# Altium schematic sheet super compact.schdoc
size 292 x 204 mm; Device: A_A4; Symbol: A_A4; Name: A_A4; @Project Name: Roborock fan driver with tacho frequency divider; REV: 1.0; Date: 2024-04-24; Sheet: 1/1; Draw By: David Buezas; Company: Your Company; Convert to PCB: yes; Add into BOM: yes; @Page No: 1; @Page Count: 1; @Schematic Name: Schematic_2; @Board Name: Super compact; @Update Date: 2025-03-17; @Create Time: 09:06:17; @Update Time: 10:07:00; @Page Name: super compact; @Create Date: 2025-03-17
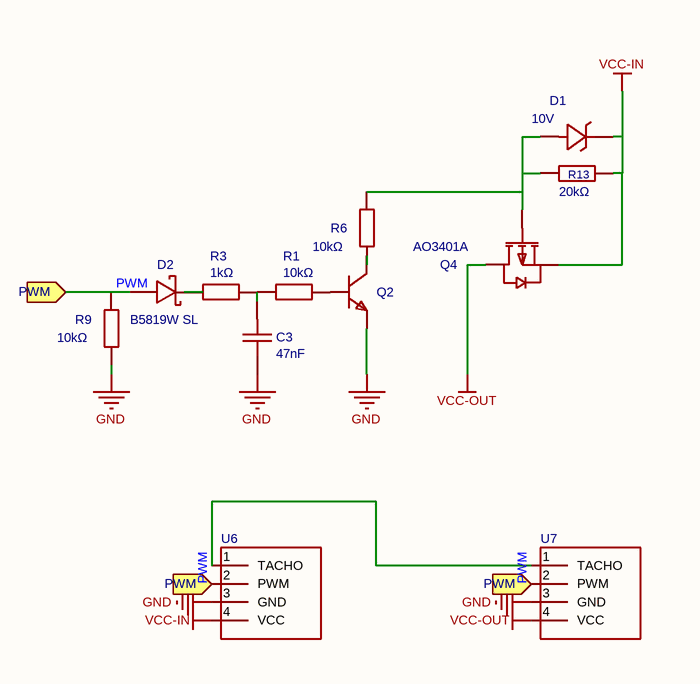
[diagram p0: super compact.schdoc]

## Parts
C3  47nF  [C0603]
D1  Zener Voltage(Nom): 10V  [SOD-123_L2.7-W1.6-LS3.7-RD]  (hidden comment: MMSZ5240B)
D2  B5819W SL  [SOD-123_L2.7-W1.6-LS3.7-RD-1]
Q2  SS8050(RANGE:200-350)  [SOT-23-3_L2.9-W1.3-P1.90-LS2.4-BR]  (value not drawn)
Q4  AO3401A  [SOT-23_L2.9-W1.3-P1.90-LS2.4-BR]
R1  10kΩ  [R0603]
R3  1kΩ  [R0603]
R6  10kΩ  [R0603]
R9  10kΩ  [R0603]
R13  20kΩ  [R0603]
U6  (no value)  [4P solder pads]
U7  (no value)  [4P solder pads mirrored]

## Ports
PWM (in)

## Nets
GND: C3.1 Q2.2(E) R9.1 U6.3(GND) U7.3(GND)
VCC-IN: D1.1(K) Q4.2(S) R13.2 U6.4(VCC)
VCC-OUT: Q4.3(D) U7.4(VCC)
PWM: D2.2(+) R9.2 U6.2(PWM) U7.2(PWM) ; port PWM
NetC3_2: C3.2 R1.1 R3.2
NetD1_2: D1.2(A) Q4.1(G) R6.2 R13.1
NetD2_1: D2.1(-) R3.1
NetQ2_1: Q2.1(B) R1.2
NetQ2_3: Q2.3(C) R6.1
NetU6_1: U6.1(TACHO) U7.1(TACHO)

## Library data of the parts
C3 = CL10B473KB8NNNC: Capacitance: Tolerance:±10% Tolerance:±10% Voltage Rated: Temperature Coefficient:; Manufacturer: SAMSUNG(三星); Symbol: CL05A105KA5NQNC; Convert to PCB: yes; ModelId: 624118aa3cc7497086c383c2d72e0852; ModelName: C0603_L1.6-W0.8-H0.8; ModelTransform: 62.992,31.496,0,0,0,0,0,0,0; Tolerance: ±10%
D1 = MMSZ5240B_C19077425: Diode Configuration:Independent Type Zener Voltage(Nom):10V Reverse Leakage Current (Ir):3uA@8V Zener Voltage(Range):9.5V~10.5V Zener Voltage(Range):9.5V~10.5V Pd - Power Dissipation(Pd):500mW Impedance(Zzt):17Ω; Manufacturer: 宏嘉诚; Convert to PCB: yes; ModelId: 31ae3d5c025440ebafdeabfabec0ebeb; ModelName: SOD-123_L2.7-W1.6-H1.4-LS3.7; ModelTransform: 146.026,62.992,0,180,0,0,0.0005,0,0; Reverse Leakage Current (Ir): 3uA@8V; Pd - Power Dissipation(Pd): 500mW; Impedance(Zzt): 17Ω
D2 = B5819W SL: Forward Voltage (Vf@If):600mV@1A Reverse Voltage (Vr):40V Rectified Current:1A; Manufacturer: CJ(江苏长电/长晶); Symbol: B5819W_C8598; Convert to PCB: yes; ModelId: 5a61cd31046d4447ba73169a45a0935b; ModelTransform: 151.575,66.929,0,0,0,0,0,0,0; Reverse Voltage (Vr): 40V; Rectified Current: 1A
Q2 = SS8050(RANGE:200-350)_C2150: Transistor Type: Collector Current (Ic): Collector-Emitter Breakdown Voltage (Vceo): Power Dissipation (Pd): DC Current Gain (hFE@Ic,Vce):200@800mA,1V DC Current Gain (hFE@Ic,Vce):200@800mA,1V Transition Frequency (fT):100MHz Collector Cut-Off Current (Ic; Manufacturer: CJ(江苏长电/长晶); Symbol: SS8050_C2150; Convert to PCB: yes; ModelId: 62a57c6760504a01965db6419a6d07df; ModelName: SOT-23-3P_L2.9-W1.3-H1.0-LS2.4-P0.95; ModelTransform: 98.425,114.173,0,180,0,0,0.0005,-0.0005,0; Transition Frequency (fT): 100MHz; Collector Cut-Off Current (Icbo): 100nA; Collector-Emitter Saturation Voltage (VCE(sat)@Ic,Ib): 500mV@800mA,80mA
Q4 = AO3401A_C15127: Type:1 Piece P-Channel Drain Source Voltage (Vdss): Continuous Drain Current (Id): Drain Source On Resistance (RDS(on)@Vgs,Id):44mΩ@10V,4.3A Power Dissipation (Pd): Gate Threshold Voltage (Vgs(th)@Id):1.3V@250uA Total Gate Charge (Qg@Vgs):12.2nC@4.5V Inpu; Manufacturer: AOS; AddInBom: yes; ModelId: 62a57c6760504a01965db6419a6d07df; ModelName: SOT-23-3P_L2.9-W1.3-H1.0-LS2.4-P0.95; ModelTransform: 98.64468,114.173,0,180,0,0,0,0,0; Input Capacitance (Ciss@Vds): 1.2nF@15V
R1 R6 R9 = 0603WAF1002T5E: Type:Thick Film Resistors Resistance:10kΩ Tolerance:±1% Tolerance:±1% Power(Watts): Overload Voltage (Max): Temperature Coefficient:±100ppm/℃ Temperature Coefficient:±100ppm/℃ Operating Temperature Range:-55℃~+155℃ Operating Temperature Range:-55℃~+155℃; Manufacturer: UNI-ROYAL(厚声); Convert to PCB: yes; ModelId: 112863783b5b41f1b5254f87eedc7932; ModelTransform: 31.8897,63.7794,0,90,0,0,0,0,0; Tolerance: ±1%
R3 = 0603WAF1001T5E: Type:Thick Film Resistors Resistance:1kΩ Tolerance:±1% Tolerance:±1% Power(Watts): Overload Voltage (Max): Temperature Coefficient:±100ppm/℃ Temperature Coefficient:±100ppm/℃ Operating Temperature Range:-55℃~+155℃ Operating Temperature Range:-55℃~+155℃; Manufacturer: UNI-ROYAL(厚声); Convert to PCB: yes; ModelId: 112863783b5b41f1b5254f87eedc7932; ModelTransform: 31.8897,63.7794,0,90,0,0,0,0,0; Tolerance: ±1%
R13 = 0603WAF2002T5E: Type:Thick Film Resistors Resistance:20kΩ Tolerance:±1% Tolerance:±1% Power(Watts): Overload Voltage (Max): Temperature Coefficient:±100ppm/℃ Temperature Coefficient:±100ppm/℃ Operating Temperature Range:-55℃~+155℃ Operating Temperature Range:-55℃~+155℃; Manufacturer: UNI-ROYAL(厚声); AddInBom: yes; ModelId: 112863783b5b41f1b5254f87eedc7932; ModelTransform: 31.8897,63.7794,0,90,0,0,0,0,0; Tolerance: ±1%
U6 U7 = 4P solder pads: AddInBom: no; ConvertToPcb: yes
